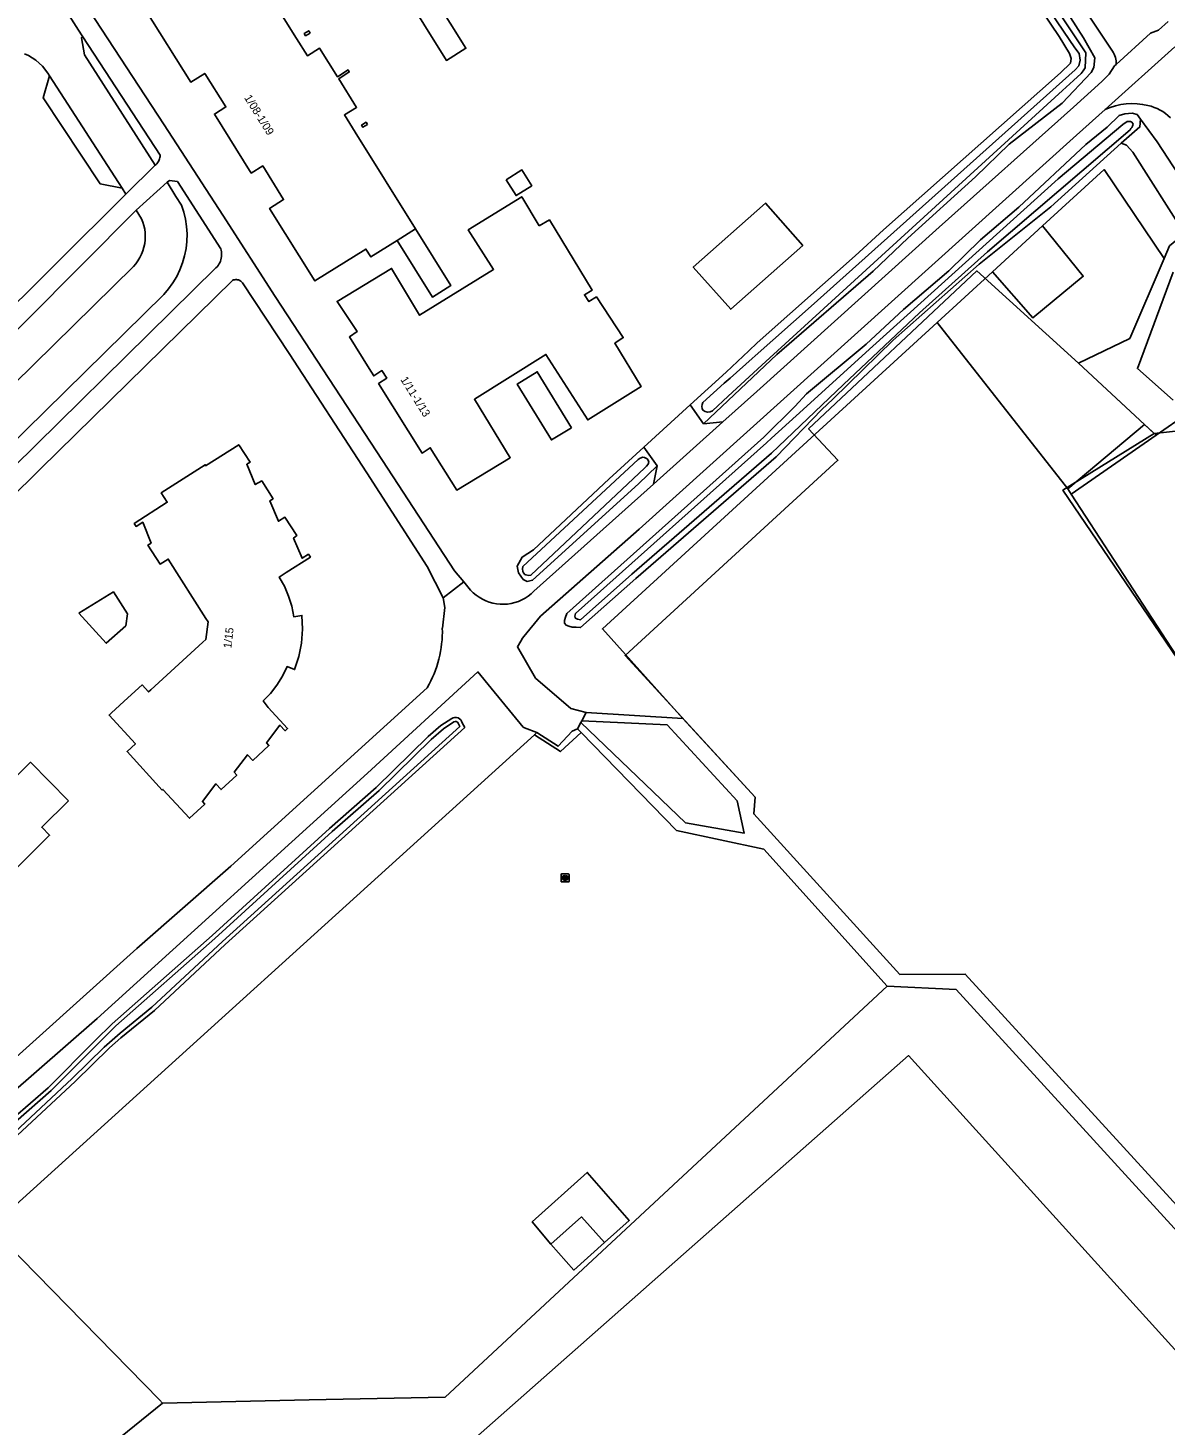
# Model space of a CAD drawing. Extents: x 162791 to 163827, y 385795 to 386523.
# Drawn here: x 163143.1 to 163285.1, y 385996.9 to 386171.4 of the extents above; entities that cross this region are included whole.
import ezdxf

# ---------------------------------------------------------------- set-up
doc = ezdxf.new("R2010")
doc.units = 0
for name, color, linetype in [('IMGEO_Erf', 7, 'Continuous'), ('IMGEO_Grasland_overig', 7, 'Continuous'), ('IMGEO_Groenvoorziening', 7, 'Continuous'), ('IMGEO_Hek', 7, 'Continuous'), ('IMGEO_Loofbos', 7, 'Continuous'), ('IMGEO_Pand', 7, 'Continuous'), ('IMGEO_Pand_nummerreeks', 7, 'Continuous'), ('IMGEO_Parkeervlak_open', 7, 'Continuous'), ('IMGEO_Rijbaan_lokaal_gesloten', 7, 'Continuous'), ('IMGEO_Rijbaan_lokaal_onverhard', 7, 'Continuous'), ('IMGEO_Rioolput', 7, 'Continuous'), ('IMGEO_Voetpad_gesloten', 7, 'Continuous'), ('IMGEO_Voetpad_halfverhard', 7, 'Continuous'), ('IMGEO_Voetpad_open', 7, 'Continuous'), ('IMGEO_Waterloop', 7, 'Continuous'), ('IMGEO_Woonerf_gesloten', 7, 'Continuous'), ('IMGEO_Woonerf_open', 7, 'Continuous')]:
    doc.layers.add(name, color=color, linetype=linetype)

msp = doc.modelspace()

# ---------------------------------------------------------------- linework, layer by layer
at = {"layer": 'IMGEO_Erf'}
for points in [[(163248.69, 386204.78), (163271.93, 386170.32), (163273.21, 386168.2), (163273.43, 386167.56), (163273.33, 386167), (163272.09, 386165.77), (163249.96, 386146.19), (163246.44, 386142.91), (163234.2, 386132.07), (163233.14, 386131.06), (163230.33, 386128.39), (163225.82, 386124.33)], [(163227.51, 386121.95), (163231.34, 386125.58), (163235.14, 386129.17), (163236.66, 386130.61), (163248.68, 386141.01), (163253.02, 386145.15), (163261.47, 386152.78), (163265.69, 386156.89), (163272.29, 386162.01), (163275.93, 386165.82), (163276.27, 386166.44), (163276.37, 386167.66), (163274.97, 386170.16), (163270.07, 386177.82)], [(163221.72, 386116.68), (163219.39, 386114.43), (163206.15, 386102.4), (163205.49, 386102.26), (163204.99, 386102.48), (163204.37, 386103.32), (163204.21, 386104.14), (163204.85, 386105.3), (163206.27, 386106.2), (163215.71, 386115.05), (163220.04, 386119.02)]]:
    msp.add_lwpolyline(points, dxfattribs=at)
at = {"layer": 'IMGEO_Grasland_overig'}
for points in [[(163138.14, 386029.7), (163149, 386039.8), (163153.29, 386044), (163154.73, 386045.24), (163158.92, 386048.66), (163167.75, 386056.89), (163197.68, 386084)], [(163196.05, 386085.12), (163194.71, 386084.25), (163193.12, 386082.89), (163186.62, 386076.52), (163180.77, 386071.38), (163166.13, 386058.04), (163153.62, 386046.98), (163151.53, 386044.91), (163145.66, 386039.01), (163141.24, 386035.15)], [(163197.68, 386084), (163197.37, 386084.6)], [(163206.68, 386083.38), (163206.37, 386083.1), (163138.45, 386021.55), (163159.54, 386000), (163159.93, 385999.61)]]:
    msp.add_lwpolyline(points, dxfattribs=at)
msp.add_arc((163196.52, 386084.4), 0.865, 13.1277, 123.3595, dxfattribs=at)
at = {"layer": 'IMGEO_Groenvoorziening'}
for points in [[(163282.07, 386160), (163281.65, 386160.58), (163281.03, 386160.76), (163280.13, 386160.68), (163279.41, 386160.44), (163277.93, 386159.01), (163275.25, 386156.83), (163266.87, 386149.02), (163262.11, 386144.94), (163258.13, 386141.07), (163252.49, 386136.23), (163247.8, 386131.9), (163240.38, 386125.67), (163238.92, 386124.09), (163235.04, 386120.27), (163210.41, 386098.25), (163210.24, 386097.8), (163210.14, 386097.39), (163210.15, 386097.04), (163210.33, 386096.8), (163210.66, 386096.65), (163211.09, 386096.56), (163211.6, 386096.52), (163212.14, 386096.49), (163219.03, 386102.63), (163236.58, 386117.81), (163242.27, 386123.72), (163243.63, 386125.03), (163251.2, 386132.39), (163261.93, 386141.88), (163270.86, 386149.04), (163279.67, 386157.01)], [(163285.04, 386142.59), (163277.53, 386153.7), (163269.85, 386146.66)], [(163269.85, 386146.66), (163263.61, 386140.95)], [(163263.61, 386140.95), (163268.63, 386135.2), (163274.92, 386140.38), (163269.85, 386146.66)], [(163263.61, 386140.95), (163256.7, 386134.62)], [(163256.7, 386134.62), (163214.87, 386096.32), (163224.9, 386085.15)], [(163273.02, 386113.8), (163256.7, 386134.62)], [(163282.58, 386121.87), (163273.02, 386113.8)], [(163273.42, 386113.17), (163284.02, 386120.54)], [(163273.42, 386113.17), (163273.02, 386113.8)], [(163300.65, 386095.94), (163289.51, 386088.43), (163273.42, 386113.17)], [(163215.13, 386019.65), (163218.23, 386022.42), (163212.98, 386028.42), (163206.11, 386022.23), (163208.42, 386019.45)]]:
    msp.add_lwpolyline(points, dxfattribs=at)
at = {"layer": 'IMGEO_Hek'}
for points in [[(163224.28, 386085.84), (163217.7, 386093.01), (163244.29, 386117.39), (163240.62, 386121.31), (163261.64, 386141.04), (163274.35, 386129.51)], [(163274.35, 386129.51), (163283.79, 386120.75)], [(163294, 386121.85), (163308.03, 386100.91), (163289.51, 386088.43), (163272.38, 386113.67), (163283.79, 386120.75)], [(163290.29, 386121.45), (163283.79, 386120.75)], [(163298.64, 386011.14), (163276.82, 386035.01), (163260.19, 386053.19), (163252.01, 386053.15), (163233.78, 386073.2), (163233.96, 386075.3), (163224.28, 386085.84)], [(163159.93, 385999.61), (163159.54, 386000), (163138.45, 386021.55), (163206.37, 386083.1), (163209.63, 386080.99), (163212.23, 386083.36)], [(163212.23, 386083.36), (163224.12, 386071.15), (163235.03, 386068.8), (163250.44, 386051.71)], [(163250.44, 386051.71), (163195.25, 386000.36), (163178.24, 386000), (163159.93, 385999.61)]]:
    msp.add_lwpolyline(points, dxfattribs=at)
at = {"layer": 'IMGEO_Loofbos'}
for points in [[(163159.93, 385999.61), (163178.24, 386000), (163195.25, 386000.36), (163250.44, 386051.71)], [(163191.89, 385988.96), (163253.1, 386043.01), (163299.96, 385991.27)], [(163159.93, 385999.61), (163134.06, 385978.71), (163130.4, 385976.29)]]:
    msp.add_lwpolyline(points, dxfattribs=at)
at = {"layer": 'IMGEO_Pand'}
for points in [[(163169.11, 386182.15), (163176.67, 386170.08), (163178.03, 386167.92), (163179.55, 386168.87), (163181.77, 386165.31), (163183.1, 386166.15), (163183.25, 386165.9), (163181.93, 386165.06), (163184.16, 386161.48), (163182.65, 386160.53), (163184, 386158.38), (163191.54, 386146.29)], [(163189.73, 386176.43), (163195.39, 386167.34), (163197.83, 386168.86), (163192.17, 386177.95), (163189.73, 386176.43)], [(163189.22, 386144.84), (163185.95, 386142.79), (163185.33, 386143.77), (163178.97, 386139.79), (163173.3, 386148.86), (163175.05, 386149.95), (163172.44, 386154.16), (163171.01, 386153.27), (163166.41, 386160.64), (163167.84, 386161.53), (163165.2, 386165.72), (163163.46, 386164.63), (163157.78, 386173.71)], [(163178.36, 386170.75), (163177.8, 386170.42), (163177.64, 386170.69), (163178.2, 386171.04), (163178.36, 386170.75)], [(163185.52, 386159.33), (163184.95, 386158.99), (163184.79, 386159.27), (163185.35, 386159.61), (163185.52, 386159.33)], [(163202.85, 386152.44), (163204.08, 386150.46), (163206.05, 386151.68), (163204.82, 386153.66), (163202.85, 386152.44)], [(163206.99, 386146.68), (163208.26, 386147.41), (163213.58, 386138.63), (163212.63, 386138.06), (163213.18, 386137.21), (163214.13, 386137.8), (163217.48, 386132.71), (163216.42, 386132), (163219.72, 386126.62), (163213.04, 386122.44), (163207.82, 386130.62), (163198.88, 386125.01), (163203.35, 386117.7), (163196.67, 386113.67), (163193.36, 386118.95), (163192.35, 386118.29), (163186.91, 386126.96), (163187.94, 386127.66), (163187.33, 386128.6), (163186.31, 386127.92), (163185.73, 386128.86), (163183.27, 386132.8), (163184.26, 386133.48), (163181.74, 386137.24), (163188.54, 386141.35), (163192.03, 386135.51), (163201.28, 386141.24), (163198.12, 386146.17), (163204.79, 386150.31), (163206.99, 386146.68)], [(163239.9, 386144.24), (163230.9, 386136.25), (163226.22, 386141.53), (163235.23, 386149.52), (163239.9, 386144.24)], [(163191.54, 386146.29), (163195.95, 386139.23), (163193.63, 386137.78), (163189.22, 386144.84)], [(163189.22, 386144.84), (163191.54, 386146.29)], [(163211.01, 386121.46), (163208.5, 386119.93), (163204.23, 386126.9), (163206.74, 386128.44), (163211.01, 386121.46)], [(163164.96, 386094.65), (163165.34, 386095), (163165.62, 386097.21), (163165.35, 386097.62), (163160.64, 386105.04), (163159.62, 386104.42), (163158.1, 386106.8), (163158.5, 386107.05), (163157.45, 386109.64), (163156.62, 386109.13), (163156.4, 386109.48), (163160.52, 386112.14), (163159.77, 386113.31), (163165.26, 386116.82), (163165.3, 386116.7), (163169.45, 386119.33), (163170.86, 386117.14), (163170.45, 386116.9), (163171.5, 386114.35), (163172.32, 386114.82), (163173.73, 386112.59), (163173.35, 386112.33), (163174.4, 386109.77), (163175.22, 386110.27), (163176.69, 386107.98), (163176.3, 386107.66), (163177.35, 386105.14), (163178.16, 386105.64), (163178.39, 386105.29), (163175.37, 386103.35), (163174.51, 386102.8), (163175.16, 386101.65), (163175.68, 386100.43), (163176.07, 386099.16), (163176.31, 386097.85), (163177.33, 386098), (163177.43, 386096.29), (163177.3, 386094.56), (163176.97, 386092.86), (163176.43, 386091.23), (163175.48, 386091.61), (163174.91, 386090.43), (163174.22, 386089.31), (163173.41, 386088.26), (163172.5, 386087.32), (163173.12, 386086.51), (163175.55, 386083.89), (163175.26, 386083.6), (163174.59, 386084.31), (163172.92, 386082.1), (163173.21, 386081.74), (163171.21, 386079.9), (163170.56, 386080.61), (163168.89, 386078.41), (163169.19, 386078.05), (163167.24, 386076.25), (163166.59, 386076.97), (163164.91, 386074.77), (163165.21, 386074.41), (163163.29, 386072.66), (163159.97, 386076.28), (163159.9, 386076.18), (163155.51, 386080.99), (163156.55, 386081.95), (163153.25, 386085.56), (163153.55, 386085.85), (163155.6, 386087.71), (163157.38, 386089.33), (163158.18, 386088.45), (163158.48, 386088.72), (163158.98, 386089.18), (163164.96, 386094.65)], [(163149.49, 386098.27), (163153.8, 386100.95), (163155.57, 386098.19), (163155.34, 386096.71), (163152.89, 386094.53), (163149.49, 386098.27)], [(163133.37, 386069.72), (163143.42, 386079.66), (163148.19, 386074.84)], [(163148.19, 386074.84), (163144.85, 386071.54), (163145.83, 386070.54), (163139.3, 386064.09)], [(163208.42, 386019.45), (163212.25, 386022.87), (163215.13, 386019.65)], [(163215.13, 386019.65), (163211.29, 386016.23), (163208.42, 386019.45)]]:
    msp.add_lwpolyline(points, dxfattribs=at)
at = {"layer": 'IMGEO_Parkeervlak_open'}
for points in [[(163154.87, 386151.38), (163152.13, 386151.94), (163145.02, 386162.68), (163145.81, 386165.42)], [(163145.81, 386165.42), (163154.87, 386151.38)]]:
    msp.add_lwpolyline(points, dxfattribs=at)
at = {"layer": 'IMGEO_Rijbaan_lokaal_gesloten'}
for points in [[(163285.54, 386172.19), (163284.33, 386171.11), (163283.34, 386170.74), (163279.05, 386166.85)], [(163277.65, 386161.21), (163286.36, 386169.05)], [(163279.05, 386166.85), (163278.85, 386166.67), (163278.16, 386165.64), (163277.24, 386164.71), (163273.7, 386161.52), (163256.94, 386146.49), (163234.16, 386126), (163229.93, 386122.18)], [(163212.83, 386085.88), (163210.94, 386086.38), (163206.53, 386090.17), (163204.25, 386094.07), (163204.69, 386094.81), (163204.9, 386095.15), (163205.05, 386095.39), (163207.12, 386097.9), (163219.47, 386108.78), (163274.09, 386158.01), (163277.65, 386161.21)], [(163229.93, 386122.18), (163221.25, 386114.4)], [(163221.25, 386114.4), (163206.31, 386101.03), (163205.97, 386100.71), (163205.6, 386100.42), (163205.21, 386100.17), (163204.8, 386099.95), (163204.38, 386099.76), (163203.94, 386099.61), (163203.49, 386099.5), (163203.03, 386099.43), (163202.56, 386099.4), (163202.1, 386099.41), (163201.64, 386099.46), (163201.18, 386099.54), (163200.73, 386099.67), (163200.3, 386099.83), (163199.88, 386100.03), (163199.48, 386100.27), (163199.1, 386100.54), (163198.74, 386100.84), (163198.41, 386101.17), (163197.55, 386102.2)], [(163197.55, 386102.2), (163194.99, 386100.2)], [(163194.88, 386096.4), (163195.18, 386099), (163194.99, 386100.2)], [(163133.3, 386031.52), (163151.76, 386047.67), (163185.55, 386078.28), (163199.32, 386090.95), (163200.98, 386088.92), (163204.99, 386084.04), (163205.13, 386083.98), (163206.68, 386083.38)], [(163129.32, 386031.83), (163130.71, 386032.99), (163156.73, 386056.38), (163168.44, 386066.69), (163193, 386088.98)], [(163212.83, 386085.88), (163212.28, 386084.84)], [(163211.76, 386083.84), (163211.09, 386083.55), (163209.34, 386081.66), (163206.68, 386083.38)], [(163212.18, 386084.63), (163211.76, 386083.84)], [(163212.18, 386084.63), (163212.28, 386084.84)]]:
    msp.add_lwpolyline(points, dxfattribs=at)
for centre, radius, start, end in [((163281.02, 386153.84), 8.11, 75.8257, 114.567), ((163281.83, 386156.2), 5.63, 45.0317, 77.9283), ((163180.7, 386096.03), 14.18, 330.1509, 1.4972)]:
    msp.add_arc(centre, radius, start, end, dxfattribs=at)
at = {"layer": 'IMGEO_Rijbaan_lokaal_onverhard'}
msp.add_lwpolyline([(163242.34, 386222.83), (163278.57, 386168.48)], dxfattribs=at)
msp.add_arc((163276.46, 386166.97), 2.6, 357.4335, 35.6423, dxfattribs=at)
at = {"layer": 'IMGEO_Rioolput'}
for p, q in [((163209.71, 386064.79), (163209.71, 386065.65)), ((163209.78, 386065.72), (163210.64, 386065.72)), ((163210.64, 386064.72), (163209.78, 386064.72)), ((163210.22, 386064.94), (163210.19, 386064.94)), ((163210.2, 386065.5), (163210.22, 386065.5)), ((163210.71, 386065.65), (163210.71, 386064.79))]:
    msp.add_line(p, q, dxfattribs=at)
for points in [[(163209.71, 386064.79), (163209.71, 386065.65)], [(163209.78, 386065.72), (163210.64, 386065.72)], [(163210.64, 386064.72), (163209.78, 386064.72)], [(163210.3, 386065.42), (163210.05, 386065.42), (163210.05, 386065.02)], [(163210.05, 386065.02), (163210.17, 386065.02), (163210.17, 386065.18), (163210.18, 386065.18)], [(163210.22, 386065.34), (163210.17, 386065.34), (163210.17, 386065.26)], [(163210.17, 386065.26), (163210.22, 386065.26)], [(163210.23, 386065.15), (163210.3, 386065.02), (163210.44, 386065.02), (163210.37, 386065.15)], [(163210.71, 386065.65), (163210.71, 386064.79)]]:
    msp.add_lwpolyline(points, dxfattribs=at)
for centre, radius, start, end in [((163209.79, 386065.64), 0.0765, 91.552, 178.448), ((163209.79, 386065.64), 0.0765, 91.552, 178.448), ((163209.79, 386064.79), 0.0765, 181.552, 268.448), ((163209.79, 386064.79), 0.0765, 181.552, 268.448), ((163210.18, 386065.13), 0.0533, 26.0293, 88.6989), ((163210.23, 386065.24), 0.0964, 77.0061, 93.1865), ((163210.21, 386065.45), 0.19, 274.7715, 282.9687), ((163210.24, 386065.3), 0.0378, 276.6634, 79.6772), ((163210.3, 386065.31), 0.109, 350.3612, 89.416), ((163210.3, 386065.31), 0.112, 277.5842, 350.9817), ((163210.28, 386065.09), 0.108, 29.5134, 73.7905), ((163210.63, 386065.64), 0.0765, 1.552, 88.448), ((163210.63, 386065.64), 0.0765, 1.552, 88.448), ((163210.63, 386064.79), 0.0765, 271.552, 358.448), ((163210.63, 386064.79), 0.0765, 271.552, 358.448)]:
    msp.add_arc(centre, radius, start, end, dxfattribs=at)
for centre, major_axis, ratio, start_param, end_param in [((163210.2, 386065.22), (-0.387, 0.002), 0.722429, 4.712389, 7.853982), ((163210.22, 386065.22), (-0.39, 0.002), 0.717154, 1.570796, 4.712389)]:
    msp.add_ellipse(centre, major_axis=major_axis, ratio=ratio, start_param=start_param, end_param=end_param, dxfattribs=at)
at = {"layer": 'IMGEO_Voetpad_gesloten'}
for points in [[(163287.59, 386145.73), (163285.72, 386144.16), (163285.04, 386142.59)], [(163285.04, 386142.59), (163280.73, 386132.59), (163274.35, 386129.51), (163282.58, 386121.87)], [(163286.14, 386140.89), (163281.69, 386128.84), (163286.16, 386124.89)], [(163284.02, 386120.54), (163287.98, 386123.29)], [(163282.58, 386121.87), (163284.02, 386120.54)]]:
    msp.add_lwpolyline(points, dxfattribs=at)
at = {"layer": 'IMGEO_Voetpad_halfverhard'}
for points in [[(163224.9, 386085.15), (163212.83, 386085.88)], [(163250.44, 386051.71), (163235.03, 386068.8), (163224.12, 386071.15), (163212.23, 386083.36), (163211.76, 386083.84)], [(163212.28, 386084.84), (163222.94, 386084.35), (163231.7, 386074.83), (163232.59, 386070.82), (163225.25, 386072.11), (163212.18, 386084.63)], [(163298.64, 386011.14), (163276.82, 386035.01), (163260.19, 386053.19), (163252.01, 386053.15), (163233.78, 386073.2), (163233.96, 386075.3), (163224.9, 386085.15)], [(163250.44, 386051.71), (163259.07, 386051.27), (163303, 386003.14), (163313.74, 386005.83)]]:
    msp.add_lwpolyline(points, dxfattribs=at)
at = {"layer": 'IMGEO_Voetpad_open'}
for points in [[(163220.04, 386119.02), (163225.82, 386124.33)], [(163225.82, 386124.33), (163227.51, 386121.95)], [(163227.51, 386121.95), (163229.93, 386122.18)], [(163221.72, 386116.68), (163220.04, 386119.02)], [(163221.25, 386114.4), (163221.72, 386116.68)]]:
    msp.add_lwpolyline(points, dxfattribs=at)
at = {"layer": 'IMGEO_Waterloop'}
for points in [[(163237.48, 386222.5), (163237.35, 386222.72), (163237.3, 386222.9), (163237.35, 386223.22), (163237.48, 386223.45), (163237.62, 386223.57), (163237.92, 386223.64), (163238.44, 386223.52), (163275.25, 386168.27), (163275.18, 386166.43), (163274.92, 386166.02), (163274.67, 386165.69), (163273.71, 386164.82), (163272.34, 386163.57), (163235.78, 386130.19), (163234.78, 386129.26), (163230.58, 386125.39), (163228.62, 386123.58)], [(163227.42, 386124.6), (163230.07, 386127.03), (163230.82, 386127.65), (163233.56, 386130.11), (163233.95, 386130.45), (163240.94, 386136.66), (163273.9, 386166.17), (163274.36, 386166.68), (163274.54, 386167.36), (163274.4, 386168.21), (163273.87, 386168.93), (163237.48, 386222.5)], [(163280.4, 386159.71), (163280.56, 386159.73), (163280.71, 386159.73), (163280.83, 386159.7), (163280.99, 386159.61), (163281.13, 386159.44), (163281.15, 386159.38), (163281.14, 386159.24), (163281.09, 386159.11), (163281, 386158.97), (163280.89, 386158.83), (163280.77, 386158.69), (163262.96, 386143.42), (163254.47, 386135.79), (163244.97, 386126.86), (163239.62, 386121.74), (163236.88, 386119.12), (163236.01, 386118.29), (163218.55, 386103.18), (163212.13, 386097.46), (163211.77, 386097.53), (163211.5, 386097.66), (163211.45, 386097.73), (163211.43, 386097.91), (163211.49, 386098.24), (163235.35, 386119.57), (163235.99, 386120.14), (163239.06, 386122.93), (163248.64, 386131.63), (163271.79, 386152.54), (163279.86, 386159.33), (163280.4, 386159.71)], [(163282.07, 386160), (163282, 386159.04), (163279.67, 386157.01)], [(163290.19, 386147.92), (163284.14, 386157.16), (163282.07, 386160)], [(163279.67, 386157.01), (163280.33, 386156.77), (163281.11, 386155.88), (163287.59, 386145.73)], [(163219.35, 386117.47), (163219.59, 386117.64), (163219.91, 386117.76), (163220.12, 386117.75), (163220.44, 386117.58), (163220.58, 386117.4), (163220.65, 386117.15), (163220.57, 386116.89), (163220.39, 386116.66), (163220.15, 386116.45), (163205.95, 386103.03), (163205.68, 386103), (163205.3, 386103.06), (163205.19, 386103.13), (163205.01, 386103.33), (163204.93, 386103.51), (163204.89, 386103.84), (163204.93, 386104.11), (163219.35, 386117.47)], [(163196.85, 386084.55), (163197.05, 386084.11), (163167.4, 386057.27), (163158.59, 386049.05), (163154.65, 386045.83), (163152.62, 386044.06), (163148.65, 386040.17), (163138.18, 386030.42)], [(163141.57, 386034.75), (163146, 386038.64), (163151.93, 386044.59), (163152, 386044.66), (163152.44, 386045.09), (163154.11, 386046.74), (163166.47, 386057.66), (163181.11, 386071), (163186.97, 386076.15), (163193.47, 386082.52), (163195.01, 386083.84), (163196.33, 386084.7)]]:
    msp.add_lwpolyline(points, dxfattribs=at)
for centre, radius, start, end in [((163228.18, 386124.12), 0.904, 147.4262, 212.6913), ((163228.05, 386124.37), 0.973, 229.5124, 305.9178), ((163196.52, 386084.4), 0.355, 24.3105, 123.7696)]:
    msp.add_arc(centre, radius, start, end, dxfattribs=at)
at = {"layer": 'IMGEO_Woonerf_gesloten'}
for points in [[(163145.58, 386177.19), (163145.62, 386177.15), (163149.82, 386170.54), (163149.98, 386170.29)], [(163150.73, 386173.68), (163160.14, 386159.28), (163167.48, 386147.99), (163174, 386137.85), (163187.42, 386117.38), (163196.41, 386103.58), (163197.55, 386102.2)], [(163149.98, 386170.29), (163159.63, 386155.49), (163159.62, 386155.35), (163159.6, 386155.2), (163159.57, 386155.06), (163159.52, 386154.93), (163159.46, 386154.79), (163159.39, 386154.67), (163159.32, 386154.55), (163159.23, 386154.44), (163159.13, 386154.33), (163159.02, 386154.24)], [(163159.02, 386154.24), (163155.34, 386150.64)], [(163160.51, 386152.14), (163160.79, 386152.33), (163161.79, 386152.23), (163167.2, 386143.82), (163167.25, 386143.63), (163167.29, 386143.43), (163167.3, 386143.23), (163167.31, 386143.03), (163167.29, 386142.83), (163167.26, 386142.64), (163167.21, 386142.44), (163167.15, 386142.25), (163167.07, 386142.07), (163166.97, 386141.89), (163166.86, 386141.73), (163166.74, 386141.57), (163166.6, 386141.42), (163135.7, 386111.04), (163135.22, 386110.58), (163135.12, 386110.69)], [(163156.62, 386148.64), (163160.51, 386152.14)], [(163078.62, 386073.9), (163090.95, 386086.25), (163109.57, 386104.88), (163137.82, 386133.23), (163155.34, 386150.64)], [(163083.47, 386068.77), (163082.46, 386069.73), (163081.9, 386070.42), (163081.78, 386070.7), (163081.68, 386070.98), (163081.6, 386071.27), (163081.55, 386071.57), (163081.53, 386071.87), (163081.53, 386072.18), (163081.56, 386072.48), (163081.62, 386072.78), (163081.7, 386073.07), (163081.81, 386073.35), (163081.94, 386073.62), (163082.1, 386073.88), (163082.27, 386074.13), (163082.47, 386074.36), (163097.04, 386089.07), (163117.96, 386109.83), (163142.94, 386134.85), (163156.62, 386148.64)], [(163194.99, 386100.2), (163193, 386104.13), (163185.45, 386115.82), (163175.75, 386130.73), (163169.9, 386139.57), (163169.84, 386139.63), (163169.78, 386139.69), (163169.71, 386139.75), (163169.64, 386139.8), (163169.57, 386139.84), (163169.49, 386139.88), (163169.41, 386139.91), (163169.32, 386139.93), (163169.24, 386139.95), (163169.15, 386139.96), (163169.07, 386139.96), (163168.98, 386139.95), (163168.89, 386139.94), (163168.81, 386139.92), (163168.73, 386139.89), (163168.65, 386139.86), (163144.69, 386116.33), (163116.89, 386088.83)]]:
    msp.add_lwpolyline(points, dxfattribs=at)
at = {"layer": 'IMGEO_Woonerf_open'}
for points in [[(163159.02, 386154.24), (163150.19, 386168.03), (163149.8, 386170.17), (163149.98, 386170.29)], [(163145.81, 386165.42), (163145.61, 386165.73), (163144.93, 386166.62), (163144.53, 386167.01), (163144.11, 386167.36), (163143.65, 386167.67), (163143.18, 386167.94), (163142.67, 386168.17)], [(163160.51, 386152.14), (163161.59, 386150.35), (163162.28, 386149.27), (163162.57, 386148.39), (163162.79, 386147.5), (163162.93, 386146.59), (163162.99, 386145.66), (163162.97, 386144.74), (163162.87, 386143.83), (163162.69, 386142.92), (163162.44, 386142.04), (163162.11, 386141.18), (163161.71, 386140.35), (163161.23, 386139.56), (163160.69, 386138.81), (163160.09, 386138.11), (163135.42, 386113.88)], [(163155.34, 386150.64), (163154.87, 386151.38)], [(163123.87, 386109.74), (163156.29, 386141.59), (163156.59, 386141.94), (163156.86, 386142.32), (163157.1, 386142.71), (163157.3, 386143.13), (163157.47, 386143.56), (163157.6, 386144), (163157.7, 386144.45), (163157.76, 386144.91), (163157.77, 386145.36), (163157.76, 386145.82), (163157.7, 386146.27), (163157.6, 386146.71), (163157.47, 386147.14), (163157.3, 386147.56), (163156.62, 386148.64)]]:
    msp.add_lwpolyline(points, dxfattribs=at)

# ---------------------------------------------------------------- texts
at = {"layer": 'IMGEO_Pand_nummerreeks'}
for s, rotation, p in [('1/08-1/09', 301.8906, (163170.09, 386162.68)), ('1/11-1/13', 302.0744, (163189.6, 386127.48)), ('1/15', 83.0159, (163168.51, 386093.85))]:
    msp.add_text(s, height=1, rotation=rotation, dxfattribs=at).set_placement(p)

doc.saveas('drawing.dxf')
